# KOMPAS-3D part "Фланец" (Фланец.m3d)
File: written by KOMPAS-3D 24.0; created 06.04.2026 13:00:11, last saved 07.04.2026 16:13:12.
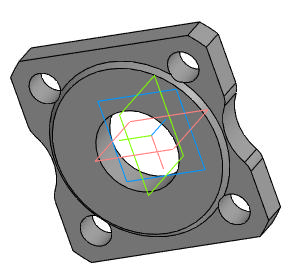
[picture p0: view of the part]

Document properties: Автор: R2D2; Полное имя файла: E:\Работа\Зайцев\Солянка\VSR1-13V-PED-F Клапан запорно-регулирующий DN.ru\DN50\исходные материалы\Фланец.m3d

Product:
- Component [standard]: (unnamed)  | qty 1  | Материал: ВЧ40 ГОСТ 7293-85 (density 7200 kg/m3); Масса: 2.58; additional columns: 50-16-01-2-B-ВЧ40-II-dв 61,5; Фланец; ГОСТ 33259-2015
- Part/product: Фланец
    Масса: 1.756734

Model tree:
1. Эскиз:6
2. Элемент выдавливания:6
3. Эскиз:7  (with: Ребро.Элемент выдавливания:6)
4. Элемент выдавливания:7
5. Зеркальный массив:2
6. Экземпляр ( 1 )
7. Экземпляр ( 2 )  (with: Элемент выдавливания:7)
8. Эскиз:8
9. Элемент выдавливания:8
     Расстояние 2 = 20
10. Скругление:2  (with: Ребро.Элемент выдавливания:8)
     Радиус = 10

Expressions: v520+20
Referenced files in C:\Program Files\ASCON\KOMPAS-3D v24\Libs\PolynomLib\DATA\vault\Methods\Kompas\3D\: PLib_Flange_GOST_33259_1401.m3d
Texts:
  BOSimple***Material:38d6725a-5efe-48e1-b177-a7817acb862a
  BOSimple***PART:f01f30e9-fcaa-80c4-4432-b1a020f57568***SHORTLOC:B6A6_23E38AE8DB154823[II;2;Круглый;50;16;61,5;0;ВЧ40 ГОСТ 7293-85]
  Ch34
  Плоскость XY.Начало координат
  Ось Z.Начало координат
  Plane ZX. Origin
  Плоскость ZX.Начало координат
